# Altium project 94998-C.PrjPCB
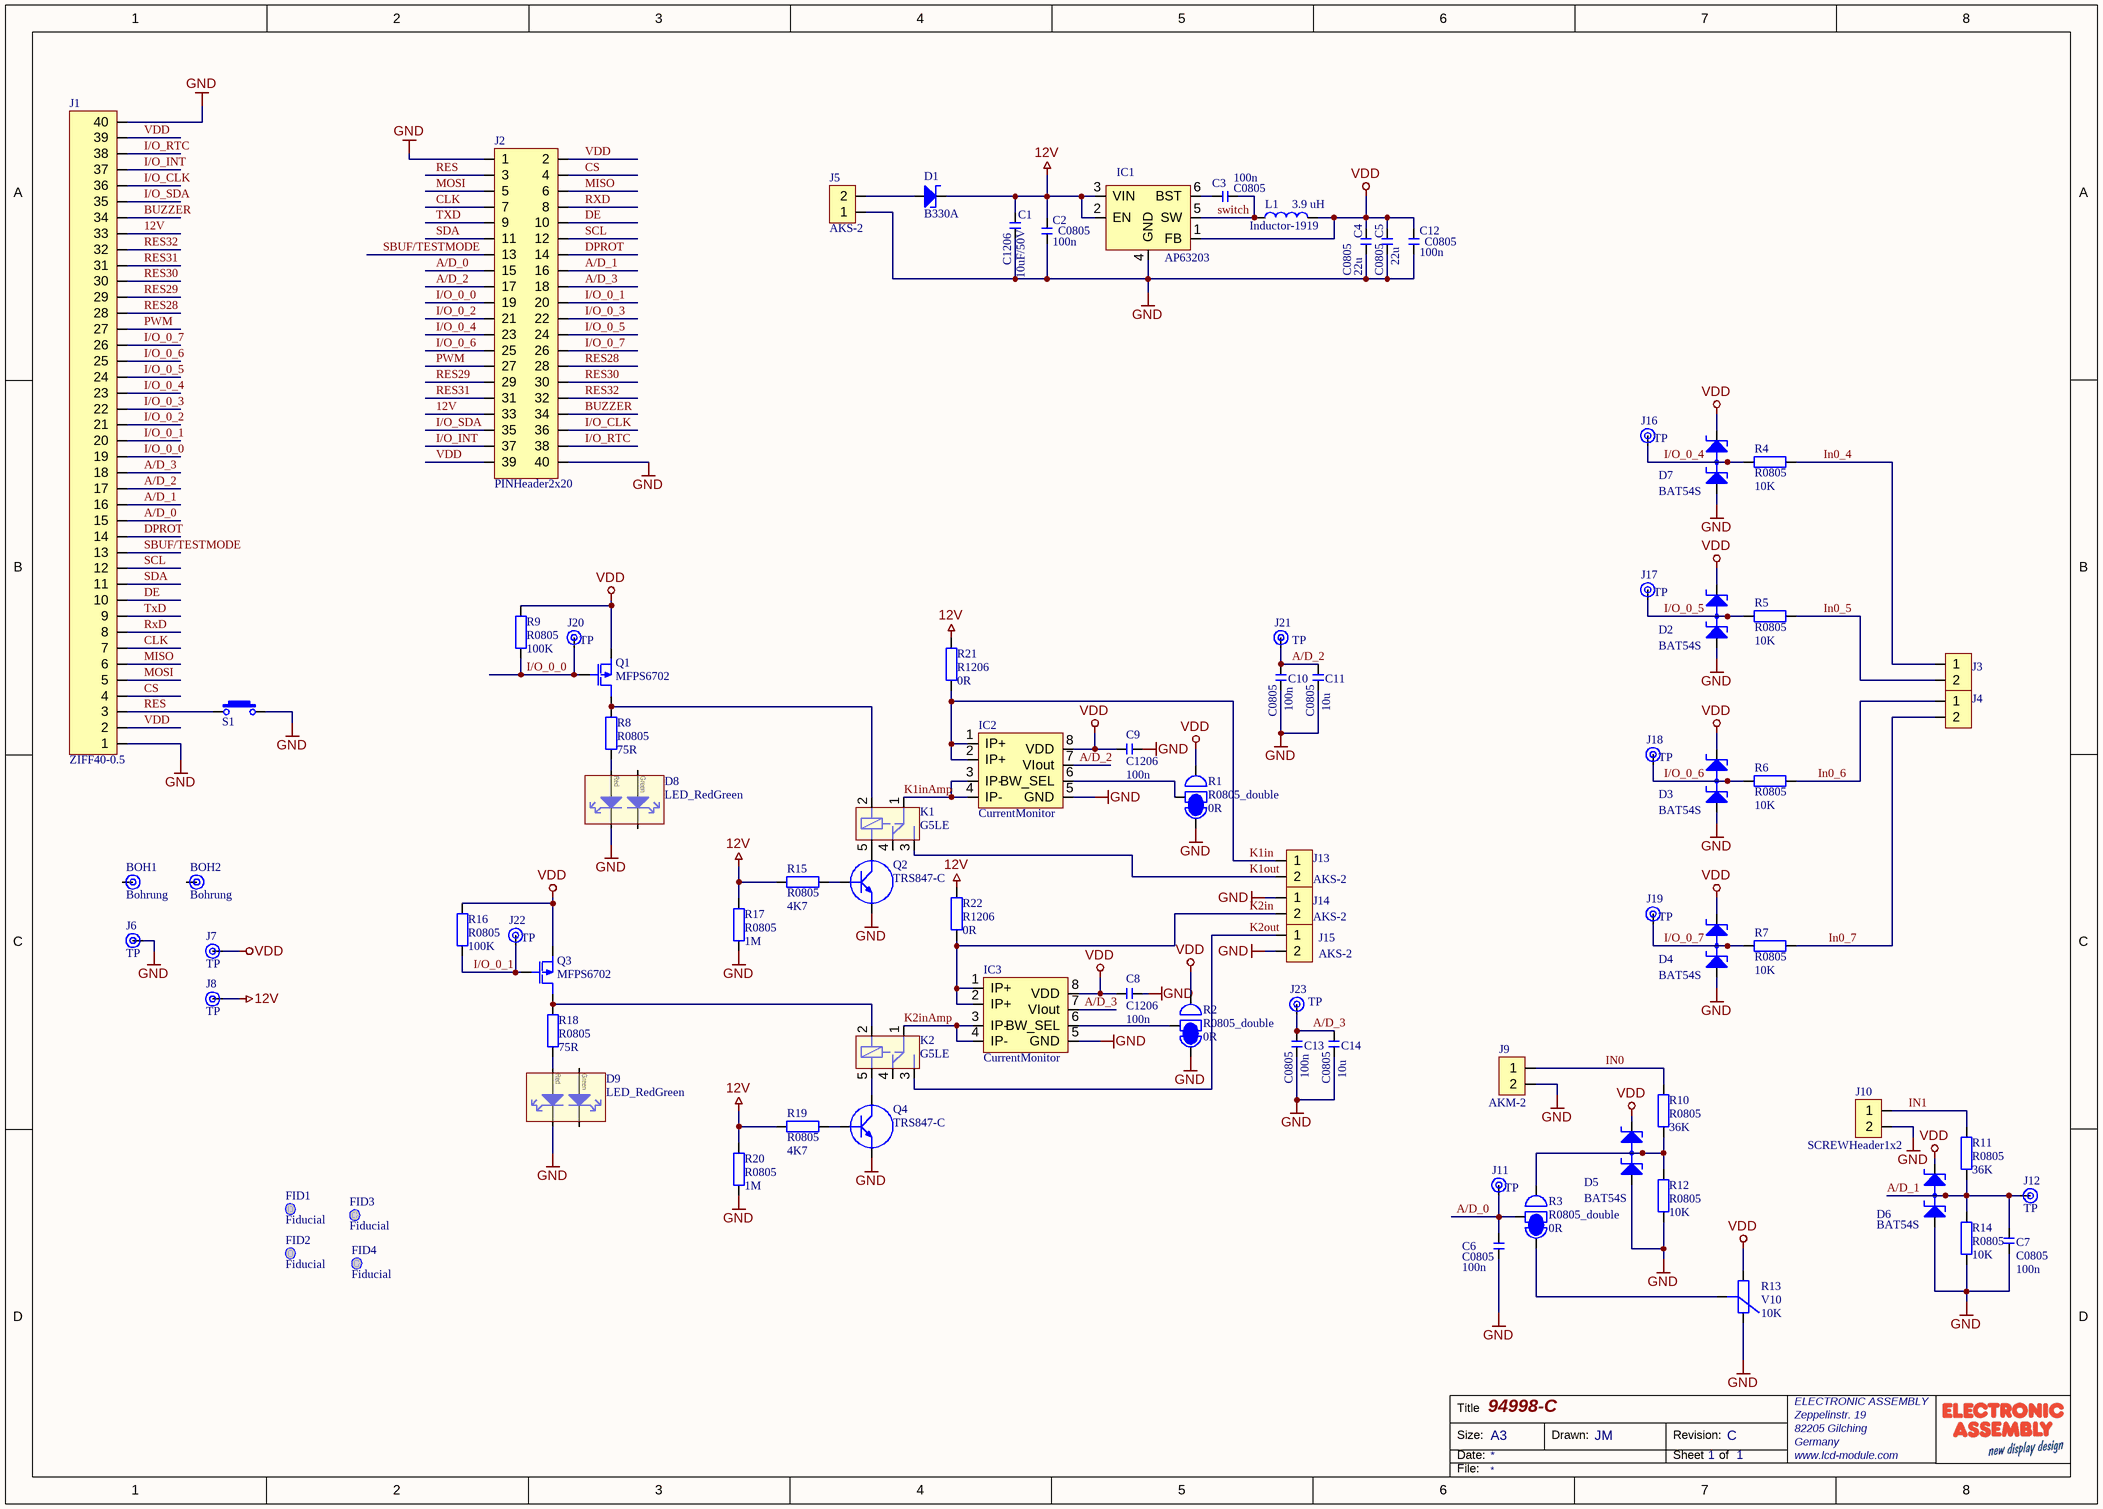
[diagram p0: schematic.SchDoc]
Projekt: 94998-C; Rev: C; Zeichner: JM
1 sheet, 85 parts. Net scope: global (net labels, ports and power ports of the same name join across sheets).
Board file: board.PcbDoc

## Sheet schematic.SchDoc
size A3; Organization: ELECTRONIC ASSEMBLY; Address1: Zeppelinstr. 19; Address2: 82205 Gilching; Address3: Germany; Address4: www.lcd-module.com; DocumentNumber: 1; SheetNumber: 1; SheetTotal: 1

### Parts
BOH1  Bohrung  [BOH_3_2]  (no BOM)
BOH2  Bohrung  [BOH_3_2]  (no BOM)
C1  C1206  value 10uF/50V  [C1206]
C2  C0805  value 100n  [C0805]
C3  C0805  value 100n  [C0805]
C4  C0805  value 22u  [C0805]
C5  C0805  value 22u  [C0805]
C6  C0805  value 100n  [C0805]
C7  C0805  value 100n  [C0805]
C8  C1206  value 100n  [C1206]
C9  C1206  value 100n  [C1206]
C10  C0805  value 100n  [C0805]
C11  C0805  value 10u  [C0805]
C12  C0805  value 100n  [C0805]
C13  C0805  value 100n  [C0805]
C14  C0805  value 10u  [C0805]
D1  B330A  [SMA]
D2  BAT54S  [SOT23-3]
D3  BAT54S  [SOT23-3]
D4  BAT54S  [SOT23-3]
D5  BAT54S  [SOT23-3]
D6  BAT54S  [SOT23-3]
D7  BAT54S  [SOT23-3]
D8  LED_RedGreen  [LEDDUO1210]
D9  LED_RedGreen  [LEDDUO1210]
FID1  Fiducial  [Fiducial]  (no BOM)
FID2  Fiducial  [Fiducial]  (no BOM)
FID3  Fiducial  [Fiducial]  (no BOM)
FID4  Fiducial  [Fiducial]  (no BOM)
IC1  AP63203  [TSOT26]
IC2  CurrentMonitor  [SOIC8_current]
IC3  CurrentMonitor  [SOIC8_current]
J1  ZIFF40-0.5  [ZIFF40-0.5 - LONG]
J2  PINHeader2x20  [PINHDR2X20]
J3  SCREWHeader1x2  [SCREWHDR1X2]  (value not drawn)
J4  SCREWHeader1x2  [SCREWHDR1X2]  (value not drawn)
J5  AKS-2  [SCREWHDR1X2_Big]
J6  TP  [PAD50/65]  (no BOM)
J7  TP  [PAD06/15]  (no BOM)
J8  TP  [PAD06/15]  (no BOM)
J9  AKM-2  [SCREWHDR1X2]
J10  SCREWHeader1x2  [SCREWHDR1X2]
J11  TP  [PAD06/15]  (no BOM)
J12  TP  [PAD06/15]  (no BOM)
J13  AKS-2  [SCREWHDR1X2_Big]
J14  AKS-2  [SCREWHDR1X2_Big]
J15  AKS-2  [SCREWHDR1X2_Big]
J16  TP  [PAD06/15]  (no BOM)
J17  TP  [PAD06/15]  (no BOM)
J18  TP  [PAD06/15]  (no BOM)
J19  TP  [PAD06/15]  (no BOM)
J20  TP  [PAD06/15]  (no BOM)
J21  TP  [PAD06/15]  (no BOM)
J22  TP  [PAD06/15]  (no BOM)
J23  TP  [PAD06/15]  (no BOM)
K1  G5LE  [G5LE]
K2  G5LE  [G5LE]
L1  Inductor-1919  value 3.9 uH  [L_1919]
Q1  MFPS6702  [TSOP-6]
Q2  TRS847-C  [SOT23-3]
Q3  MFPS6702  [TSOP-6]
Q4  TRS847-C  [SOT23-3]
R1  R0805_double  value 0R  [R0805_double]
R2  R0805_double  value 0R  [R0805_double]
R3  R0805_double  value 0R  [R0805_double]
R4  R0805  value 10K  [R0805]
R5  R0805  value 10K  [R0805]
R6  R0805  value 10K  [R0805]
R7  R0805  value 10K  [R0805]
R8  R0805  value 75R  [R0805]
R9  R0805  value 100K  [R0805]
R10  R0805  value 36K  [R0805]
R11  R0805  value 36K  [R0805]
R12  R0805  value 10K  [R0805]
R13  V10  value 10K  [V10]
R14  R0805  value 10K  [R0805]
R15  R0805  value 4K7  [R0805]
R16  R0805  value 100K  [R0805]
R17  R0805  value 1M  [R0805]
R18  R0805  value 75R  [R0805]
R19  R0805  value 4K7  [R0805]
R20  R0805  value 1M  [R0805]
R21  R1206  value 0R  [R1206]
R22  R1206  value 0R  [R1206]
S1  SMD Taster  [TASTER_SMD]  (value not drawn)

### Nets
12V: C1.2 C2.2 D1.2(C) IC1.2(EN) IC1.3(VIN) J1.33 J2.33 J8.1 R15.2 R17.1 R19.2 R20.1 R21.1 R22.1
GND: C1.1 C2.1 C4.1 C5.1 C6.1 C7.1 C8.2 C9.2 C10.1 C11.1 C12.1 C13.1 C14.1 D2.1(A) D3.1(A) D4.1(A) D5.1(A) D6.1(A) D7.1(A) D8.3(C_Red) D9.3(C_Red) IC1.4(GND) IC2.5(GND) IC3.5(GND) J1.1 J1.40 J2.1 J2.40 J5.1 J6.1 J9.2 J10.2 J14.1 J15.2 Q2.2(E) Q4.2(E) R1.1 R2.1 R12.1 R13.1(A) R14.1 R17.2 R20.2 S1.2
VDD: C4.2 C5.2 C8.1 C9.1 C12.2 D2.2(C) D3.2(C) D4.2(C) D5.2(C) D6.2(C) D7.2(C) IC1.1(FB) IC2.8(VDD) IC3.8(VDD) J1.2 J1.39 J2.2 J2.39 J7.1 L1.2 Q1.4(S) Q3.4(S) R1.3 R2.3 R9.1 R13.2(E) R16.2
A/D_0: C6.2 J1.15 J2.15 J11.1 R3.2
A/D_1: C7.2 D6.3(A/C) J1.16 J2.16 J12.1 R11.1 R14.2
A/D_2: C10.2 C11.2 IC2.7(VIout) J1.17 J2.17 J21.1
A/D_3: C13.2 C14.2 IC3.7(VIout) J1.18 J2.18 J23.1
BUZZER: J1.34 J2.34
CLK: J1.7 J2.7
CS: J1.4 J2.4
DE: J1.10 J2.10
DPROT: J1.14 J2.14
I/O_0_0: J1.19 J2.19 J20.1 Q1.3(G) R9.2
I/O_0_1: J1.20 J2.20 J22.1 Q3.3(G) R16.1
I/O_0_2: J1.21 J2.21
I/O_0_3: J1.22 J2.22
I/O_0_4: D7.3(A/C) J1.23 J2.23 J16.1 R4.2
I/O_0_5: D2.3(A/C) J1.24 J2.24 J17.1 R5.2
I/O_0_6: D3.3(A/C) J1.25 J2.25 J18.1 R6.2
I/O_0_7: D4.3(A/C) J1.26 J2.26 J19.1 R7.2
I/O_CLK: J1.36 J2.36
I/O_INT: J1.37 J2.37
I/O_RTC: J1.38 J2.38
I/O_SDA: J1.35 J2.35
IN0: J9.1 R10.2
In0_4: J3.1 R4.1
In0_5: J3.2 R5.1
In0_6: J4.1 R6.1
In0_7: J4.2 R7.1
IN1: J10.1 R11.2
K1in: IC2.1(IP+) IC2.2(IP+) J13.1 R21.2
K1inAmp: IC2.3(IP-) IC2.4(IP-) K1.1(in)
K1out: J13.2 K1.3(out_off)
K2in: IC3.1(IP+) IC3.2(IP+) J14.2 R22.2
K2inAmp: IC3.3(IP-) IC3.4(IP-) K2.1(in)
K2out: J15.1 K2.3(out_off)
MISO: J1.6 J2.6
MOSI: J1.5 J2.5
PWM: J1.27 J2.27
RES: J1.3 J2.3 S1.1
RES28: J1.28 J2.28
RES29: J1.29 J2.29
RES30: J1.30 J2.30
RES31: J1.31 J2.31
RES32: J1.32 J2.32
RxD: J1.8 J2.8
SBUF/TESTMODE: J1.13 J2.13
SCL: J1.12 J2.12
SDA: J1.11 J2.11
switch: C3.1 IC1.5(SW) L1.1
TxD: J1.9 J2.9
NetC3_2: C3.2 IC1.6(BST)
NetD1_1: D1.1(A) J5.2
NetD5_3: D5.3(A/C) R3.3 R10.1 R12.2
NetD8_4: D8.4(A_Red) R8.1
NetD9_4: D9.4(A_Red) R18.1
NetIC2_6: IC2.6(BW_SEL) R1.2
NetIC3_6: IC3.6(BW_SEL) R2.2
NetK1_2: K1.2(coil1) Q1.1(D) R8.2
NetK1_5: K1.5(coil2) Q2.3(C)
NetK2_2: K2.2(coil1) Q3.1(D) R18.2
NetK2_5: K2.5(coil2) Q4.3(C)
NetQ2_1: Q2.1(B) R15.1
NetQ4_1: Q4.1(B) R19.1
NetR3_1: R3.1 R13.3(S)

Not connected (* = marked no-connect by the designer): BOH1 1; BOH2 1; D8 1(C_Green) 2(A_Green); D9 1(C_Green) 2(A_Green); K1 4(out_on); K2 4(out_on)

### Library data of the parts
C1-C14 = Capacitor
D1 = B330A: Schottky; EA_PN: DIODESB330A; Vendor1_PN: B330A-13-F
D2-D7 = BAT54S: Vendor1: ROHM Semiconductor; Vendor2: Diodes Incorporated; Vendor1_PN: BAT54SHMFHT116; Vendor2_PN: BAT54S-7-F; Value: BAT54S-7-F
D8 D9 = LED_RedGreen: LED red green 1210; EA_PN: ZLEDS020-RG; Vendor1: ROHM; Vendor1_PN: SML-020MVTT86
IC1 = AP63200: Vendor1: Diodes Incorporated; Vendor1_PN: AP63203WU-7
IC2 IC3 = ACS70331: High Sensitivity, 1 MHz, GMR-Based Current Sensor IC; Vendor1: Allegro microsystems; Vendor1_PN: ACS70331EOLCTR-005U3; Vendor2_PN: ACS722LLCTR-05AB-T
J1 = ZIFF40-0.5: EA_PN: WF050-40S (Bottom contact) / WF050-40ST (Top contact); Vendor1: Neltron; Vendor2: Würth; Vendor1_PN: 1226-40-02 (Bottom contact) / 1226-40-03 (Top contact); Vendor2_PN: 68714014522 (Bottom contact) / 68714014022 (Top contact)
J2 = PINHeader2x20: Pin strip 2x20
J3 J4 J10 = SCREWHeader1x2: Screw terminal 1x2; EA_PN: AKM-2
J5 J13-J15 = SCREWHeader1x2_Big: Screw terminal 1x2
J9 = SCREWHeader1x2: Screw terminal 1x2
K1 K2 = G5LE: Relais; Vendor1: Omron; Vendor1_PN: G5LE-1-ASI DC3
L1 = Inductor-1919: Vendor1: Bourns; Vendor2: Würth; Vendor1_PN: SRR4028-3R9; Vendor2_PN: 7440430039
Q1 Q3 = MFPS6702: Vendor1: Vishay; Vendor1_PN: IRLMS6702TR-PBF
Q2 Q4 = TRS847-C: Vendor1: MICRONETIC; Vendor1_PN: BC 847-C SOT23
R1-R3 = Resistor_double: Resistor
R4-R12 R14-R22 = Resistor
R13 = Potentiometer: EA_PN: POT10K-L; Vendor1: PIHER; Vendor1_PN: PIH PT10MV103IPM
S1 = SW-1P7: Switch, Knackfrosch; EA_PN: TASTS-1P7MM; Vendor1: DIPTRINICS MANUFACTURING; Vendor1_PN: DTSM63N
